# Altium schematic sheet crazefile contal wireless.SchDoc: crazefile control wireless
size A4; CompanyName: 良工作室; DrawnBy: 郑良杰; Engineer: 郑良杰; Organization: 良工作室; DocumentNumber: 3; SheetNumber: 3; SheetTotal: 4
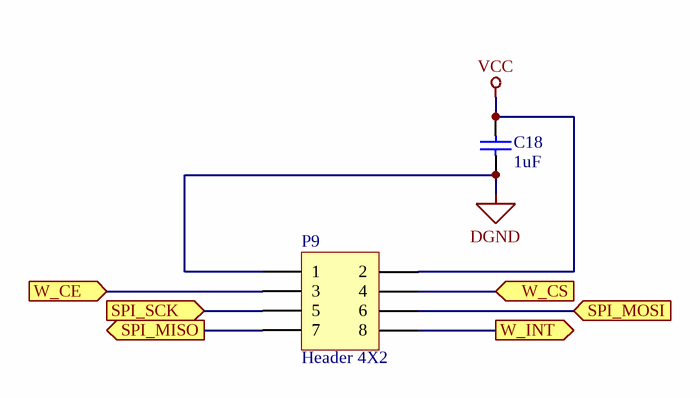
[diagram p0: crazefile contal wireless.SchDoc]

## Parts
C18  value 1uF  [CAP_0603]  (hidden comment: Cap)
P9  Header 4X2  [HDR2X4]

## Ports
SPI_MISO (out), SPI_MOSI (in), SPI_SCK (in), W_CE (in), W_CS (in), W_INT (out)

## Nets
DGND: C18.1 P9.1
VCC: C18.2 P9.2
SPI_MISO: P9.7 ; port SPI_MISO
SPI_MOSI: P9.6 ; port SPI_MOSI
SPI_SCK: P9.5 ; port SPI_SCK
W_CE: P9.3 ; port W_CE
W_CS: P9.4 ; port W_CS
W_INT: P9.8 ; port W_INT

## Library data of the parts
C18 = Cap: Capacitor
P9 = Header 4X2: Header, 4-Pin, Dual row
